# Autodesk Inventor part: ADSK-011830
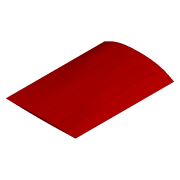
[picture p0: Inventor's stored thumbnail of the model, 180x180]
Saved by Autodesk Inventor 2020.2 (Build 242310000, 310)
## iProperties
Created: 1999-11
Part Number: ADSK-011830
Document SubType Name: Modeling
Designer: sspink
Material: Générique
Density: 1 g/cm^3
Appearance: Red(Flat)
Mass: 573.955 g
Surface Area: 717.443 cm^2
Volume: 573.955 cm^3
Control State: 0
Checked Out: False
Last Check In By: sspink
Last Check In Date: 1999-12-22
Master: False
Shininess: 0.0
Length Units: 11269
Angle Units: 11279
Time Units: 11290
Mass Units: 11283
Length Display Precision: 3
Angle Display Precision: 2
Compacted: True
Dimensions: 37x215,9x152,4 mm
Mass: 0,574 kg
DocNumber: ADSK-011830.ipt
Folder: 01 - Themengebiete\Simplification\01 - Packaging machine\
VDS_Category: 3D Komponenten
VLT_Material: Generic
Density: 0.0
Volumn: 0.0
Area: 0.0
PropertySet Name: Model Information
Author: sspink
Revision Number: -
Title: product
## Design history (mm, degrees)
sketch "Sketch4"
  geometry: L1 (-76.2, 0)-(76.2, 0) reference; L2 (-38.1, 0)-(-38.1, 14.923); L3 (-53.975, 0)-(-53.975, 10.636); L4 (53.975, 0)-(53.975, 10.636); L5 (0, 0)-(0, 18) reference; L6 (38.1, 0)-(38.1, 14.923)
  constraints: 12 end point, 4 parallel, 4 point on line, 2 horizontal, 1 midpoint, 1 perpendicular, 1 vertical, 7 other
  dimensions: "d26" = 152.4 distance of L1.start L1.end; "d27" = 38.1 distance between parallel lines of L5 L2; "d28" = 38.1 distance between parallel lines of L6 L5 (= d27); "d29" = 18 distance of L5.start L5.end; "d31" = 53.975 distance between parallel lines of L5 L4 (= d50); "d32" = 14.9225 distance of L6.start L6.end; "d33" = 10.63625 distance of L4.start L4.end; "d50" = 53.975 distance between parallel lines of L3 L5
workplane "Work Plane6"
workplane "Work Plane7"
workplane "Work Plane8"
workplane "Work Plane9"
workplane "Work Plane10"
node "Loft1" dims "d64" = 0, "d65" = 90 deg, "d66" = 0, "d67" = 90 deg, "d68" = 0, "d69" = 90 deg, "d70" = 0, "d71" = 90 deg, "d72" = 0, "d73" = 90 deg
node "Mirror1"
workplane "Work Plane16"
workplane "Work Plane17"
workplane "Work Plane18"
workplane "Work Plane19"
node "Solide1"
node "Corps solides"
node "Corps surfaciques"
sketch "Sketch5"
  geometry: L1 (0, 0)-(152.4, 0) reference; L2 (76.2, 0)-(76.2, 17.475); L3 (53.975, 0)-(53.975, 15.875); L4 (28.575, 0)-(28.575, 12.7); L5 (123.825, 0)-(123.825, 12.7); L6 (98.425, 0)-(98.425, 15.875)
  constraints: 10 end point, 6 parallel, 4 point on line, 1 midpoint, 1 perpendicular, 7 other
  dimensions: "d35" = 17.4752 distance of L2.start L2.end; "d36" = 15.875 distance of L6.start L6.end; "d38" = 22.225 distance between parallel lines of L3 L2; "d39" = 22.225 distance between parallel lines of L6 L2 (= d38); "d40" = 47.625 distance between parallel lines of L4 L2; "d41" = 47.625 distance between parallel lines of L5 L2 (= d40); "d74" = 12.7 distance of L4.start L4.end
sketch "Sketch6"
  geometry: L1 (0, 0)-(152.4, 0) reference; L2 (76.2, 0)-(76.2, 13.018); L3 (50.8, 0)-(50.8, 12.383); L4 (101.6, 0)-(101.6, 12.383); L5 (123.825, 0)-(123.825, 7.938); L6 (28.575, 0)-(28.575, 7.938)
  constraints: 10 end point, 6 parallel, 4 point on line, 1 midpoint, 1 perpendicular, 7 other
  dimensions: "d43" = 13.0175 distance of L2.start L2.end; "d44" = 12.3825 distance of L4.start L4.end; "d45" = 7.9375 distance of L5.start L5.end; "d46" = 25.4 distance between parallel lines of L4 L2; "d47" = 47.625 distance between parallel lines of L5 L2; "d48" = 25.4 distance between parallel lines of L3 L2 (= d46); "d49" = 47.625 distance between parallel lines of L6 L2 (= d47)
sketch "Sketch7"
  geometry: L1 (0, 0)-(152.4, 0) reference; L2 (76.2, 0)-(76.2, 7.938); L3 (44.45, 0)-(44.45, 7.303); L4 (34.925, 0)-(34.925, 6.35); L5 (107.95, 0)-(107.95, 7.303); L6 (120.65, 0)-(120.65, 6.35); 1 further point
  constraints: 10 end point, 6 parallel, 4 point on line, 1 midpoint, 1 perpendicular, 7 other
  dimensions: "d52" = 7.9375 distance of L2.start L2.end; "d53" = 7.3025 distance of L3.start L3.end; "d54" = 6.35 distance of L4.start L4.end; "d55" = 31.75 distance between parallel lines of L3 L2; "d56" = 31.75 distance between parallel lines of L5 L2; "d57" = 44.45 distance between parallel lines of L6 L2; "d58" = 41.275 distance between parallel lines of L4 L2
sketch "Sketch8"
  geometry: L1 (0, 0)-(152.4, 0) reference; L2 (76.2, 0)-(76.2, 1.588); L3 (47.625, 0)-(47.625, 1.27); L4 (104.775, 0)-(104.775, 1.27)
  constraints: 6 end point, 3 parallel, 2 point on line, 1 midpoint, 1 perpendicular, 5 other
  dimensions: "d60" = 1.5875 distance of L2.start L2.end; "d61" = 1.27 distance of L4.start L4.end; "d62" = 28.575 distance between parallel lines of L4 L2; "d63" = 28.575 distance between parallel lines of L2 L3 (= d62)
other parameters: "d30" = 50.8, "d34" = 53.975, "d42" = 53.975, "d51" = 53.975, "d59" = 53.975, "d79" = -76.2, "d80" = 76.2, "d81" = 18.1102, "d82" = -18.1102
